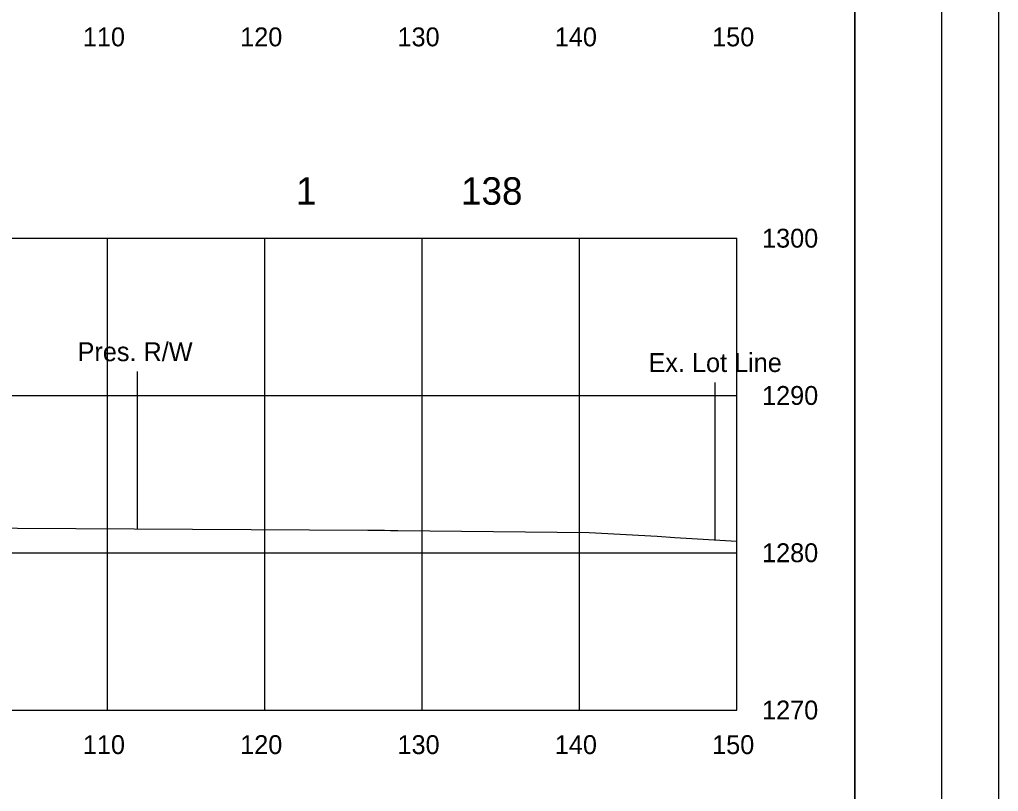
# Model space of a CAD drawing. Extents: x 2148105 to 2149976, y 144169 to 149705.
# Drawn here: x 2148517.7 to 2148579.9, y 144301.7 to 144350.8 of the extents above; entities that cross this region are included whole.
import ezdxf

# ---------------------------------------------------------------- set-up
doc = ezdxf.new("R2010")
doc.units = 0
for name, color, linetype in [('PH1a-PR-ServRd', 7, 'Continuous'), ('PR_Align_Ramp_A', 7, 'Continuous'), ('PR_Align_Ramp_E', 7, 'Continuous'), ('PR_Align_Ramp_J', 7, 'Continuous'), ('PR_Storm_Conc_Box_PH1B', 7, 'Continuous'), ('PR_Storm_Conc_Pipe_PH1B', 7, 'Continuous'), ('PR_Storm_Inlet_CICI_PH1B', 7, 'Continuous'), ('PR_Storm_MH_PH1A', 7, 'Continuous'), ('PR_Storm_MH_PH1B', 7, 'Continuous'), ('PR_Storm_Standard_Median_Drain_PH1A', 7, 'Continuous'), ('PR_Storm_Standard_Median_Drain_PH1B', 7, 'Continuous')]:
    doc.layers.add(name, color=color, linetype=linetype)

msp = doc.modelspace()

# ---------------------------------------------------------------- linework, layer by layer
at = {"layer": 'PH1a-PR-ServRd'}
msp.add_lwpolyline([(2148570.822, 144201.906), (2148255.822, 144201.906), (2148255.822, 144411.906), (2148570.822, 144411.906)], close=True, dxfattribs=at)
at = {"layer": 'PR_Align_Ramp_E'}
msp.add_lwpolyline([(2148219.947, 144425.156), (2148579.947, 144425.156), (2148579.947, 144185.156), (2148219.947, 144185.156)], close=True, dxfattribs=at)
at = {"layer": 'PR_Align_Ramp_J'}
msp.add_lwpolyline([(2148236.322, 144416.906), (2148576.322, 144416.906), (2148576.322, 144196.906), (2148236.322, 144196.906)], close=True, dxfattribs=at)
at = {"layer": 'PR_Storm_Conc_Box_PH1B'}
for p, q in [((2148263.322, 144336.906), (2148563.322, 144336.906)), ((2148523.322, 144306.906), (2148523.322, 144336.906)), ((2148533.322, 144306.906), (2148533.322, 144336.906)), ((2148543.322, 144306.906), (2148543.322, 144336.906)), ((2148553.322, 144306.906), (2148553.322, 144336.906)), ((2148563.322, 144306.906), (2148563.322, 144336.906)), ((2148263.322, 144326.906), (2148563.322, 144326.906)), ((2148263.322, 144316.906), (2148563.322, 144316.906)), ((2148263.322, 144306.906), (2148563.322, 144306.906))]:
    msp.add_line(p, q, dxfattribs=at)
at = {"layer": 'PR_Storm_Conc_Pipe_PH1B'}
msp.add_lwpolyline([(2148255.822, 144201.906), (2148570.822, 144201.906), (2148570.822, 144411.906), (2148255.822, 144411.906)], close=True, dxfattribs=at)
msp.add_lwpolyline([(2148255.822, 144201.906), (2148570.822, 144201.906), (2148570.822, 144411.906), (2148255.822, 144411.906)], close=True, dxfattribs=at)
at = {"layer": 'PR_Storm_Inlet_CICI_PH1B'}
msp.add_lwpolyline([(2148426.839, 144319.929), (2148431.899, 144319.82), (2148435.833, 144319.709), (2148464.302, 144319.01), (2148464.313, 144319.01), (2148464.337, 144319.01), (2148499.005, 144318.569), (2148539.854, 144318.339), (2148540.919, 144318.332), (2148541.313, 144318.329), (2148541.368, 144318.329), (2148541.623, 144318.326), (2148541.765, 144318.326), (2148553.943, 144318.184), (2148558.263, 144317.95), (2148559.373, 144317.876), (2148563.322, 144317.653)], dxfattribs=at)
at = {"layer": 'PR_Storm_MH_PH1A'}
msp.add_line((2148525.213, 144318.421), (2148525.213, 144328.421), dxfattribs=at)
at = {"layer": 'PR_Storm_Standard_Median_Drain_PH1A'}
msp.add_line((2148561.932, 144317.731), (2148561.932, 144327.731), dxfattribs=at)
at = {"layer": 'PR_Storm_Standard_Median_Drain_PH1B'}
for p, q in [((2148563.322, 144306.906), (2148563.322, 144336.906)), ((2148263.322, 144306.906), (2148563.322, 144306.906))]:
    msp.add_line(p, q, dxfattribs=at)

# ---------------------------------------------------------------- texts
at = {"layer": 'PR_Align_Ramp_A'}
for s, p in [('1', (2148535.298, 144339.031)), ('138', (2148545.787, 144339.031))]:
    msp.add_text(s, height=1.75, dxfattribs=at).set_placement(p)
at = {"layer": 'PR_Storm_MH_PH1A'}
msp.add_text('Pres. R/W', height=1.2, rotation=360, dxfattribs=at).set_placement((2148521.413, 144329.088))
at = {"layer": 'PR_Storm_MH_PH1B'}
for s, p in [('110', (2148521.749, 144349.106)), ('120', (2148531.749, 144349.106)), ('130', (2148541.749, 144349.106)), ('140', (2148551.749, 144349.106)), ('150', (2148561.749, 144349.106)), ('1300', (2148564.922, 144336.306)), ('1290', (2148564.922, 144326.306)), ('1280', (2148564.922, 144316.306)), ('1270', (2148564.922, 144306.306)), ('110', (2148521.749, 144304.106)), ('120', (2148531.749, 144304.106)), ('130', (2148541.749, 144304.106)), ('140', (2148551.749, 144304.106)), ('150', (2148561.749, 144304.106))]:
    msp.add_text(s, height=1.2, dxfattribs=at).set_placement(p)
at = {"layer": 'PR_Storm_Standard_Median_Drain_PH1A'}
msp.add_text('Ex. Lot Line', height=1.2, rotation=360, dxfattribs=at).set_placement((2148557.703, 144328.398))

doc.saveas('drawing.dxf')
